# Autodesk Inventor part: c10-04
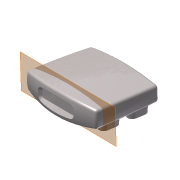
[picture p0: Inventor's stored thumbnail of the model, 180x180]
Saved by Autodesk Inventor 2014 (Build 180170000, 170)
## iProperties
Created: 2010-12
Part Number: c10-04
Material: Generic
Document SubType Name: Modeling
Designer: Thom Tremblay
Density: 1 g/cm^3
Appearance: Light Gray
Author: Thom Tremblay
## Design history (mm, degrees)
sketch "Sketch1"
  geometry: L1 (-60, -12)-(60, -12); L2 (60, -12)-(60, 12); L3 (60, 12)-(-60, 12); L4 (-60, 12)-(-60, -12); A1 r 350 centre (0, -332.819) between (60, 12) and (-60, 12); A2 r 350 centre (0, 332.819) between (-60, -12) and (60, -12); 3 further points
  constraints: 8 end point, 4 point on circle, 2 centre point, 2 midpoint, 2 parallel, 1 equal radius, 1 horizontal, 1 horizontal alignment, 1 perpendicular, 1 vertical alignment
  dimensions: "d0" = 120 distance of L3.end L2.end; "d1" = 24 distance of L2.end L1.end; "d2" = 350 radius of A1
workplane "Work Plane4"
sketch "Sketch5"
  geometry: L1 (-60, 12)-(-60, -12) reference; L2 (60, -12)-(60, 12) reference; L3 (-58, 10.314)-(-58, -10.314); L4 (58, -10.314)-(58, 10.314); A1 r 350 centre (0, 332.819) between (-60, -12) and (60, -12) reference; A2 r 350 centre (0, -332.819) between (60, 12) and (-60, 12) reference; A3 r 348 centre (0, 332.819) between (-58, -10.314) and (58, -10.314); A4 r 348 centre (0, -332.819) between (58, 10.314) and (-58, 10.314); 1 further point
  constraints: 4 end point, 4 point on circle, 2 centre point, 3 other
  dimensions: "d37" = 2 distance between parallel lines of L2 L4
sketch "Sketch6"
  geometry: L1 (-60, 0)-(60, 0); L2 (60, 0)-(58.843, 22.085); L3 (-60, 0)-(-58.779, 23.307); A1 r 691.758 centre (630.81, -36.204) between (-60, 0) and (-58, -100); A2 r 691.758 centre (-630.81, -36.204) between (58, -100) and (60, 0); 1 further point
  constraints: 6 end point, 4 point on circle, 2 centre point, 2 tangent, 1 horizontal
  dimensions: "d53" = 87 deg angle of L1 L3; "d54" = 87 deg angle of L1 L2 (= d53)
sketch "Sketch7"
  geometry: L1 (17.181, 0)-(12, 0) reference; L2 (15.181, -100)-(10.314, -100) reference; L3 (17.181, 0)-(16.768, 11.838); A1 r 911.322 centre (-893.585, -31.805) between (15.181, -100) and (17.181, 0); 1 further point
  constraints: 2 end point, 2 point on circle, 1 centre point, 1 tangent
  dimensions: "d56" = 88 deg angle of L1 L3
feature "LoftSrf2" sketch "Sketch5", "Sketch6", "Sketch7" dims "d57" = 0, "d58" = 90 deg, "d59" = 0, "d60" = 90 deg, "d61" = 0, "d62" = 90 deg, "d63" = 0, "d64" = 90 deg, "d65" = 0, "d66" = 90 deg
sketch "Sketch2"
  geometry: L1 (-75, -16)-(75, -16); L2 (-75, -60)-(75, -60); A1 r 183.781 centre (0, -183.781) between (75, -16) and (-75, -16); 2 further points
  constraints: 4 end point, 3 point on circle, 1 centre point, 1 coincident, 1 horizontal, 1 parallel
  dimensions: "d5" = 16 distance from line of point (0, 0) L1; "d7" = 60 distance from line of point (0, 0) L2; "d55" = 150 distance of L1.start L1.end
feature "RevolutionSrf1" sketch "Sketch2" dims angle "d8" = 40 deg
patch "Boundary Patch1" dims "d13" = 0, "d67" = 0, "d68" = 0, "d69" = 0, "d70" = 0
workplane "Work Plane1"
sketch "Sketch3"
  geometry: L1 (52, -85)-(52, -73); L2 (38, -73)-(38, -85); A1 r 7 centre (45, -73) between (52, -73) and (38, -73); A2 r 7 centre (45, -85) between (38, -85) and (52, -85); 1 further point
  constraints: 4 end point, 4 point on circle, 4 tangent, 2 centre point, 1 parallel, 1 vertical
  dimensions: "d15" = 12 distance of L1.start L1.end; "d16" = 7 radius of A1; "d50" = 45 horizontal distance of A1.centre point (0, 0); "d51" = 85 vertical distance of point (0, 0) A2.centre
extrude_surface "ExtrusionSrf2" sketch "Sketch3" dims "d19" = 14, "d20" = 5 deg
pattern_linear "Rectangular Pattern1" dims "d23" = 90
workplane "Work Plane2"
feature "Sculpt1"
sketch "Sketch4"
  geometry: L1 (-24.5, 6)-(24.5, 6); L2 (27.5, 3)-(27.5, -3); L3 (24.5, -6)-(-24.5, -6); L4 (-27.5, -3)-(-27.5, 3); A1 r 3 centre (-24.5, 3) between (-24.5, 6) and (-27.5, 3); A2 r 3 centre (24.5, 3) between (27.5, 3) and (24.5, 6); A3 r 3 centre (24.5, -3) between (24.5, -6) and (27.5, -3); A4 r 3 centre (-24.5, -3) between (-27.5, -3) and (-24.5, -6); 6 further points
  constraints: 8 end point, 8 point on circle, 8 tangent, 6 point on line, 4 centre point, 3 equal radius, 2 midpoint, 2 parallel, 1 horizontal, 1 horizontal alignment, 1 perpendicular, 1 vertical alignment
  dimensions: "d28" = 55 distance of point (27.5, -6) point (-27.5, -6); "d29" = 12 distance of point (27.5, 6) point (27.5, -6); "d30" = 3 radius of A1
extrude_surface "ExtrusionSrf6" sketch "Sketch4" dims "d31" = 14, "d32" = 45 deg
patch "Boundary Patch2" dims "d33" = 0, "d34" = 0
fillet "Fillet1" dims "d79" = 4, "d80" = 3, "d81" = 1
feature "Sculpt2"
node "Splitting Plane 1"
shell "Shell1" dims "d83" = 2
body "Solid1"
body "Srf2"
body "Srf3"
body "Srf4"
body "Srf5"
body "Srf6"
body "Srf7"
body "Srf8"
body "Srf9"
body "Srf11"
feature "Stitch Surface1"
body "Srf12"
extrude_surface "ExtrusionSrf3"
extrude_surface "ExtrusionSrf4"
extrude_surface "ExtrusionSrf5"
other parameters: "d14" = -24, "d52" = -6
